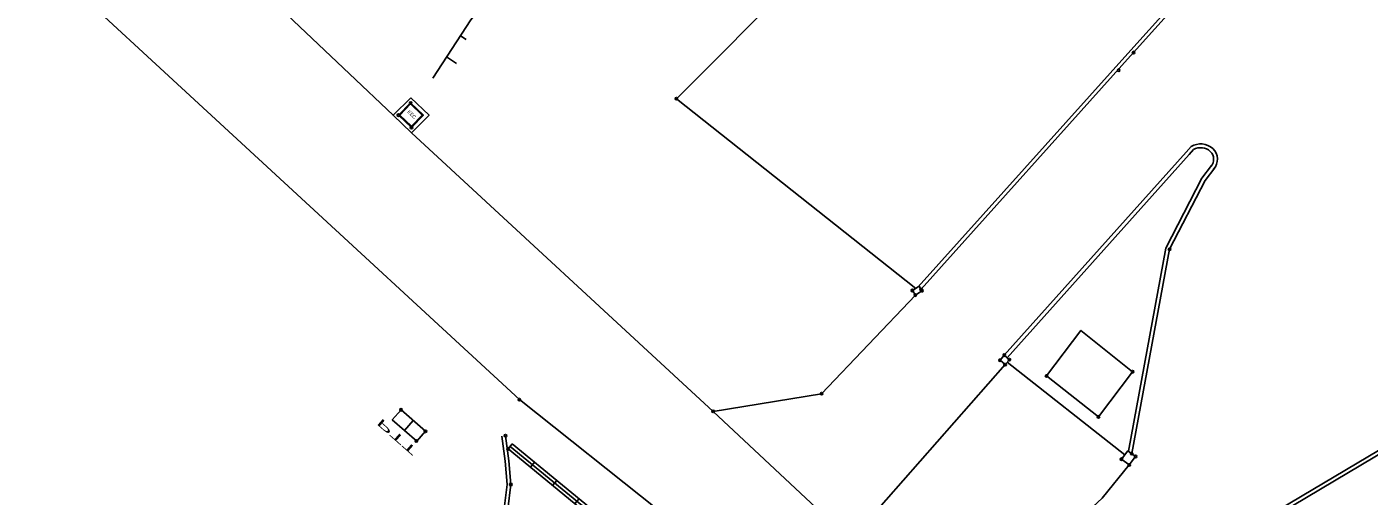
# Model space of a CAD drawing. Extents: x 344013 to 344423, y 298505 to 298795.
# Drawn here: x 344222.4 to 344275.5, y 298695.5 to 298714.1 of the extents above; entities that cross this region are included whole.
import ezdxf

# ---------------------------------------------------------------- set-up
doc = ezdxf.new("R2010")
doc.units = 0
for name, color, linetype in [('Default', 7, 'Continuous'), ('DH_CADRE -CARTOUCHE', 7, 'Continuous'), ('DH_CADRE-CARTOUCHE-NORD', 7, 'Continuous'), ('PC_CONCRETE', 7, 'Continuous'), ('PS_BOLT', 7, 'Continuous'), ('PS_SOLID', 7, 'Continuous'), ('PS_WELD', 7, 'Continuous'), ('RES_ELECTRICITE', 7, 'Continuous'), ('TOPO_POINT', 7, 'Continuous'), ('TOPO_TALUS-TERRAIN NATUREL', 7, 'Continuous'), ('VOIRIE_BORDURE', 7, 'Continuous')]:
    doc.layers.add(name, color=color, linetype=linetype)

# ---------------------------------------------------------------- blocks, each defined once
blk = doc.blocks.new('CT2')
at = {"layer": 'Default'}
blk.add_lwpolyline([(0, 0), (1, 0), (1, 1), (0, 1)], close=True, dxfattribs=at)
blk.add_lwpolyline([(0.5, 1), (0.5, 0)], dxfattribs=at)
blk.add_text('PTT', height=0.6, dxfattribs=at).set_placement((-0.3, 1.425))
blk = doc.blocks.new('RES_ELECTRICITE')
at = {"layer": 'RES_ELECTRICITE'}
for points in [[(0, 0), (0, 1), (1, 1), (1, 0)], [(0.05, 0.05), (0.05, 0.95), (0.95, 0.95), (0.95, 0.05)]]:
    blk.add_lwpolyline(points, close=True, dxfattribs=at)
blk.add_text('EEC', height=0.2, dxfattribs=at).set_placement((0.237, 0.46))
blk = doc.blocks.new('R5')
at = {"layer": 'Default'}
for p, q in [((0, 1), (0, 0)), ((1, 1), (0, 1)), ((0.2, 1), (0.2, 0)), ((0.4, 1), (0.4, 0)), ((0.6, 1), (0.6, 0)), ((0.8, 1), (0.8, 0)), ((1, 0), (1, 1)), ((0, 0), (1, 0)), ((0.6, 0), (0.6, 0))]:
    blk.add_line(p, q, dxfattribs=at)
blk = doc.blocks.new('POINT_DISPLAY')
at = {"layer": 'Default'}
blk.add_circle((0, 0), 0.05, dxfattribs=at)

msp = doc.modelspace()

# ---------------------------------------------------------------- linework, layer by layer
at = {"layer": 'DH_CADRE -CARTOUCHE'}
for points in [[(344257.792, 298703.631), (344257.675, 298703.811), (344257.413, 298703.64), (344257.53, 298703.46)], [(344261.253, 298700.902), (344261.085, 298700.705), (344260.881, 298700.88), (344261.051, 298701.079)], [(344266.246, 298697.069), (344265.995, 298696.731), (344265.689, 298696.959), (344265.941, 298697.297)]]:
    msp.add_lwpolyline(points, close=True, dxfattribs=at)
at = {"layer": 'PC_CONCRETE'}
msp.add_lwpolyline([(344241.5, 298697.468), (344245.902, 298693.849)], dxfattribs=at)
at = {"layer": 'PS_BOLT'}
msp.add_lwpolyline([(344237.561, 298711.277), (344236.864, 298710.583), (344237.595, 298709.887), (344238.291, 298710.581)], close=True, dxfattribs=at)
msp.add_lwpolyline([(344257.53, 298703.46), (344253.822, 298699.555), (344249.529, 298698.855), (344255.02, 298693.71), (344255.118, 298693.908), (344255.706, 298694.579), (344261.085, 298700.705)], dxfattribs=at)
at = {"layer": 'PS_SOLID'}
msp.add_lwpolyline([(344262.723, 298700.258), (344264.775, 298698.635), (344266.129, 298700.424), (344264.085, 298702.058)], close=True, dxfattribs=at)
at = {"layer": 'PS_WELD'}
for points in [[(344257.544, 298703.725), (344248.073, 298711.237), (344267.039, 298730.273)], [(344265.815, 298697.128), (344261.169, 298700.804)]]:
    msp.add_lwpolyline(points, dxfattribs=at)
at = {"layer": 'TOPO_TALUS-TERRAIN NATUREL'}
for p, q in [((344239.527, 298713.729), (344239.758, 298713.578)), ((344238.98, 298712.892), (344239.375, 298712.633))]:
    msp.add_line(p, q, dxfattribs=at)
msp.add_lwpolyline([(344238.432, 298712.054), (344239.938, 298714.358), (344241.185, 298715.913), (344243.24, 298717.742), (344246.077, 298720.349), (344249.189, 298723.577), (344251.671, 298726.412), (344254.067, 298728.831), (344256.737, 298731.477), (344259.433, 298734.164), (344261.244, 298736.174), (344263.396, 298738.775), (344265.304, 298740.943), (344267.298, 298743.071), (344268.251, 298744.021), (344269.173, 298745.019), (344269.173, 298745.019)], dxfattribs=at)
at = {"layer": 'VOIRIE_BORDURE'}
for p, q in [((344268.54, 298709.222), (344268.36, 298709.024)), ((344268.36, 298709.024), (344261.162, 298700.979))]:
    msp.add_line(p, q, dxfattribs=at)
for points in [[(344257.644, 298703.788), (344266.054, 298713.165), (344272.82, 298720.69), (344275.38, 298722.243), (344279.959, 298722.487), (344280.269, 298722.569)], [(344224.767, 298722.063), (344236.864, 298710.583), (344237.595, 298709.887), (344249.529, 298698.855)], [(344257.755, 298703.688), (344266.166, 298713.064), (344272.917, 298720.574), (344275.425, 298722.095), (344279.982, 298722.338), (344280.403, 298722.45)], [(344221.201, 298718.398), (344241.864, 298699.32), (344247.363, 298694.936)], [(344270.166, 298693.919), (344278.95, 298699.134), (344284.997, 298706.184), (344287.211, 298708.679), (344291.43, 298713.968)], [(344270.243, 298693.79), (344279.037, 298699.029), (344284.564, 298705.439), (344285.119, 298706.096), (344287.326, 298708.582), (344291.547, 298713.875)], [(344268.444, 298709.339), (344268.248, 298709.125), (344261.051, 298701.079)], [(344265.959, 298697.283), (344267.447, 298705.322), (344268.865, 298708.084), (344269.255, 298708.591)], [(344266.093, 298697.183), (344267.591, 298705.273), (344268.992, 298708.004), (344269.375, 298708.502)], [(344229.502, 298679.321), (344235.009, 298685.869), (344239.915, 298691.695), (344240.541, 298692.702), (344240.986, 298693.742), (344241.26, 298695.003), (344241.373, 298695.963), (344241.302, 298696.882), (344241.164, 298697.869)], [(344229.617, 298679.224), (344235.124, 298685.773), (344240.037, 298691.607), (344240.674, 298692.632), (344241.129, 298693.696), (344241.409, 298694.979), (344241.524, 298695.96), (344241.451, 298696.898), (344241.312, 298697.89)], [(344255.02, 298693.71), (344255.732, 298693.172), (344256.452, 298692.824), (344258.472, 298692.615), (344260.292, 298692.633), (344261.963, 298693.07), (344263.617, 298694.205), (344264.925, 298695.421), (344265.995, 298696.731)]]:
    msp.add_lwpolyline(points, dxfattribs=at)
for centre, radius, start, end in [((344268.821, 298708.744), 0.705, 47.0548, 122.3662), ((344268.821, 298708.744), 0.555, 47.0548, 120.4116), ((344268.91, 298708.839), 0.575, 317.5822, 47.0548), ((344268.91, 298708.839), 0.425, 317.6009, 47.0548)]:
    msp.add_arc(centre, radius, start, end, dxfattribs=at)

# ---------------------------------------------------------------- block references
at = {"layer": 'DH_CADRE-CARTOUCHE-NORD', "xscale": 1.288622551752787, "yscale": -0.5277778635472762, "rotation": -41.33376000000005}
msp.add_blockref('CT2', (344237.18, 298698.916), dxfattribs=at)
at = {"layer": 'PC_CONCRETE', "xscale": 5.698532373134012, "yscale": 0.26107124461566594, "rotation": -39.41910000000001}
msp.add_blockref('R5', (344241.417, 298697.367), dxfattribs=at)
at = {"layer": 'RES_ELECTRICITE', "xscale": 0.7081778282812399, "yscale": 0.682930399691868, "rotation": -43.60536000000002}
msp.add_blockref('RES_ELECTRICITE', (344237.079, 298710.585), dxfattribs=at)
at = {"layer": 'TOPO_POINT'}
for p in [(344266.166, 298713.064), (344265.577, 298712.365), (344237.563, 298711.067), (344248.073, 298711.237), (344237.079, 298710.585), (344237.592, 298710.097), (344267.591, 298705.273), (344257.413, 298703.64), (344257.53, 298703.46), (344257.755, 298703.688), (344257.792, 298703.631), (344260.881, 298700.88), (344261.051, 298701.079), (344261.085, 298700.705), (344261.253, 298700.902), (344262.723, 298700.258), (344266.129, 298700.424), (344241.864, 298699.32), (344253.822, 298699.555), (344237.18, 298698.916), (344249.529, 298698.855), (344264.775, 298698.635), (344238.148, 298698.065), (344237.784, 298697.682), (344241.312, 298697.89), (344241.417, 298697.367), (344265.689, 298696.959), (344266.093, 298697.183), (344266.246, 298697.069), (344265.995, 298696.731), (344241.524, 298695.96)]:
    msp.add_blockref('POINT_DISPLAY', p, dxfattribs=at)

doc.saveas('drawing.dxf')
